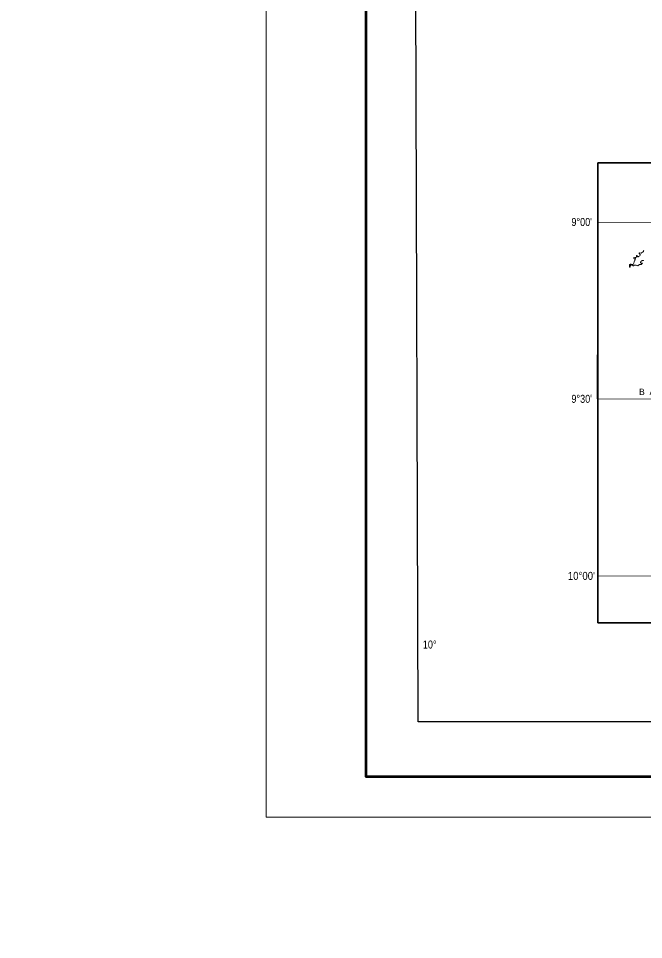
# Model space of a CAD drawing. Extents: x -1643653 to 4543381, y 1624270 to 13878484.
# Drawn here: x 538494 to 577543, y 8876229 to 8933785 of the extents above; entities that cross this region are included whole.
import ezdxf
from ezdxf.enums import TextEntityAlignment as Align

# ---------------------------------------------------------------- set-up
doc = ezdxf.new("R2010")
doc.units = 0
doc.header["$LTSCALE"] = 160
doc.linetypes.add('MEDIUM_DASHED', pattern=[4.5, 3, -1.5])
for name, color, linetype, lineweight in [('3', 7, 'Continuous', 13), ('46', 7, 'MEDIUM_DASHED', 70), ('6', 7, 'Continuous', 13), ('60', 7, 'Continuous', 13)]:
    doc.layers.add(name, color=color, linetype=linetype, lineweight=lineweight)

msp = doc.modelspace()

# ---------------------------------------------------------------- linework, layer by layer
at = {"layer": '3'}
msp.add_lwpolyline([(842807.3, 9032387.8), (842807.3, 8883887.8), (553961.7, 8883887.8), (553961.7, 9032387.8)], close=True, dxfattribs=at)
msp.add_lwpolyline([(842807.3, 9032387.8), (842807.3, 8883887.8), (553961.7, 8883887.8), (553961.7, 9032387.8)], close=True, dxfattribs=at)
at = {"layer": '3', "lineweight": 53}
msp.add_lwpolyline([(840307.3, 9029887.8), (840307.3, 8886387.8), (560211.7, 8886387.8), (560211.7, 9029887.8)], close=True, dxfattribs=at)
msp.add_lwpolyline([(840307.3, 9029887.8), (840307.3, 8886387.8), (560211.7, 8886387.8), (560211.7, 9029887.8)], close=True, dxfattribs=at)
at = {"layer": '3', "lineweight": 25}
msp.add_lwpolyline([(563033.9, 9026438.8), (793061.1, 9026438.8), (793495.6, 8889836.8), (563468.3, 8889836.8)], close=True, dxfattribs=at)
at = {"layer": '6'}
msp.add_line((574653.9, 8910009.3), (626625.7, 8909822.1), dxfattribs=at)
at = {"layer": '6', "lineweight": 35}
msp.add_lwpolyline([(574695.3, 8924769.6), (626625.7, 8924769.6), (626625.7, 8896026.7), (574695.3, 8896026.7)], close=True, dxfattribs=at)
at = {"layer": '6'}
for points in [[(585645.8, 8921027.3), (574684.9, 8921064.7), (574653.9, 8910009.3), (585614.8, 8909969.8)], [(585583.8, 8898914.4), (574695.3, 8898953.2), (574695.3, 8896026.7), (585573.6, 8896026.7)]]:
    msp.add_lwpolyline(points, close=True, dxfattribs=at)
for points in [[(574684.9, 8921064.7), (596639.8, 8920989.8), (607636.3, 8920937.2), (626625.7, 8920820.5)], [(577550.9, 8919276.7), (577542.2, 8919255.5), (577537.4, 8919219.6), (577517.1, 8919192.8), (577470.4, 8919172.4), (577423.2, 8919134.8), (577392.6, 8919123.6), (577288.8, 8919130.9), (577276.3, 8919128.8), (577268.1, 8919121), (577270.2, 8919104.2), (577283.6, 8919086), (577334.7, 8919037.1), (577339.4, 8919028), (577339, 8919010.8), (577330.4, 8918993.5), (577300, 8918957.1), (577261.1, 8918926), (577219.7, 8918900.1), (577201.5, 8918883.6), (577173.9, 8918878.9), (577161.7, 8918889.3), (577154.3, 8918912.2), (577128, 8918964), (577114.6, 8918975.2), (577102, 8918963.5), (577098.6, 8918924.1), (577103.8, 8918886.2), (577096.9, 8918865.5), (577070.2, 8918846), (577054.5, 8918844.7), (577013.1, 8918850.3), (576992.4, 8918847.3), (576950.7, 8918828.7), (576919.3, 8918818.6), (576917.4, 8918807.5), (576923.7, 8918801.2), (576943.2, 8918799.2)], [(576943.2, 8918799.2), (576959.4, 8918797.6), (577006, 8918788.1), (577033.3, 8918776.8), (577034.2, 8918768.7), (577022.6, 8918740.6), (577007, 8918721.9), (576987.5, 8918647.6), (576973.2, 8918629), (576962, 8918607), (576952.5, 8918578.3), (576936.2, 8918497.4), (576923.5, 8918455.2), (576916.6, 8918442.6), (576893.7, 8918416.7), (576869.5, 8918413.2), (576826.3, 8918412.8), (576773.5, 8918429.2), (576731.3, 8918425.5), (576706.8, 8918414.9), (576692.2, 8918402.8), (576658.1, 8918382.5), (576657.2, 8918376.5), (576657.2, 8918376.5), (576665.4, 8918346.7), (576665.4, 8918303.4), (576657.6, 8918268.8), (576660.2, 8918260.6), (576669.7, 8918252), (576674.8, 8918251.5), (576696.5, 8918271.9), (576707.8, 8918319.8), (576717.3, 8918337.2), (576738.9, 8918360.9), (576760.9, 8918373.4), (576801.8, 8918378.5), (576835.7, 8918371.3), (576854.4, 8918359.7), (576853.1, 8918356.1), (576875.8, 8918338.5), (576902.3, 8918330.7), (576914.3, 8918332.1), (576982.4, 8918362.6), (577001.8, 8918365.7), (577082.1, 8918365.2), (577124.5, 8918353.1), (577153.5, 8918337.2), (577191.5, 8918325.9), (577205.8, 8918335.4), (577215.4, 8918355.3), (577227.4, 8918369.6), (577267.3, 8918386.5), (577293.2, 8918403.3), (577336.2, 8918409.8), (577376.2, 8918406.3), (577389.6, 8918412.8), (577431.4, 8918449.4), (577465.7, 8918470.4), (577467, 8918486.4), (577449.7, 8918495.8), (577418.6, 8918492.4), (577390.5, 8918498.4), (577377.3, 8918505.5), (577361.1, 8918524.3), (577359.3, 8918565.4)], [(577359.3, 8918565.4), (577375.7, 8918596.1), (577432.8, 8918643.2), (577457.4, 8918651.9), (577500.7, 8918655.8), (577530.1, 8918668.4), (577544.6, 8918685.7)], [(574695.3, 8898953.2), (596544.3, 8898870.4), (626625.7, 8898710.8)]]:
    msp.add_lwpolyline(points, dxfattribs=at)
at = {"layer": '60', "lineweight": 25}
msp.add_spline([(814781, 9009175.5), (814787.2, 9009173.4), (814796.9, 9009173.4), (814799.4, 9009172.4), (814805.1, 9009174.5), (814805.6, 9009176.5), (814811.7, 9009179.5), (814811.7, 9009179.5), (814801.5, 9009181), (814790.7, 9009181.5), (814784.1, 9009183.1), (814777.4, 9009185.1), (814778.4, 9009175.5)], degree=3, dxfattribs=at)

# ---------------------------------------------------------------- texts
at = {"layer": '46', "width": 0.85}
msp.add_text('10°', height=500, dxfattribs=at).set_placement((564183.6, 8894414.2), align=Align.CENTER)
at = {"layer": '6'}
for s, width, p in [("9°00'", 0.85, (573677.4, 8920816.3)), ("9°30'", 0.85, (573677.4, 8909766.4)), ("10°00'", 0.9, (573657.3, 8898704.5))]:
    msp.add_text(s, height=500, dxfattribs=dict(at, width=width)).set_placement(p, align=Align.CENTER)
msp.add_text('B  A  H  I  A', height=400, dxfattribs=at).set_placement((577259.8, 8910252.7))

doc.saveas('drawing.dxf')
